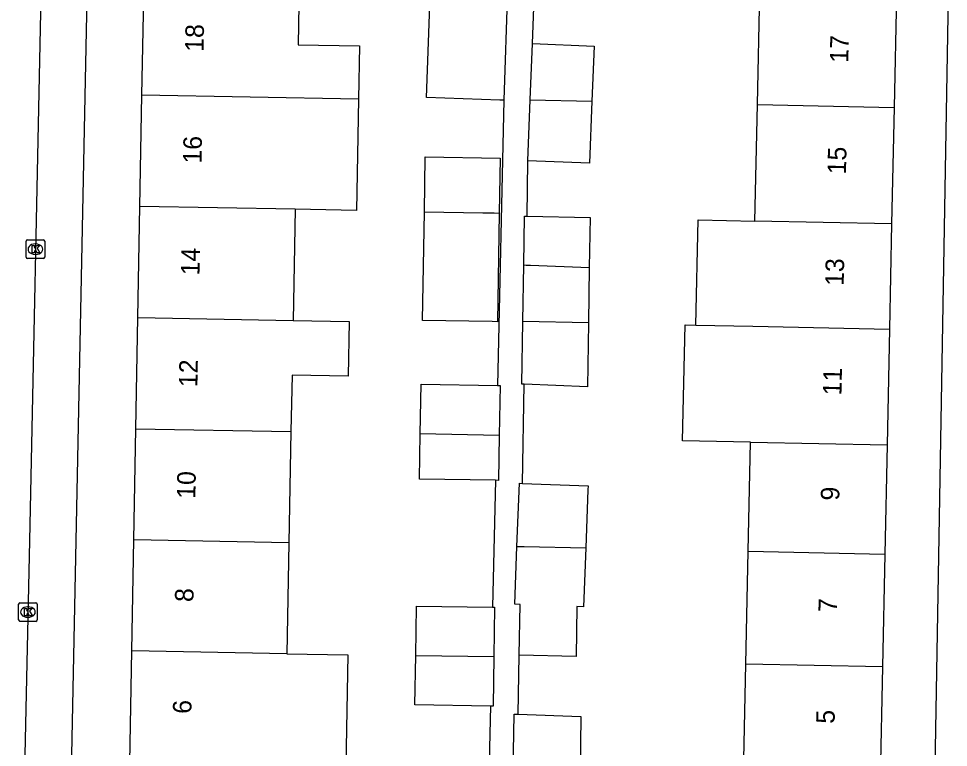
# Model space of a CAD drawing. Extents: x 160026 to 161302, y 384757 to 385701.
# Drawn here: x 160621.7 to 160671.9, y 385059.5 to 385098.8 of the extents above; entities that cross this region are included whole.
import ezdxf

# ---------------------------------------------------------------- set-up
doc = ezdxf.new("R2010")
doc.units = 0
for name, color, linetype in [('IMGEO_Kolk', 7, 'Continuous'), ('IMGEO_Pand', 7, 'Continuous'), ('IMGEO_Pand_nummerreeks', 7, 'Continuous'), ('IMGEO_Rijbaan_lokaal_open', 7, 'Continuous'), ('IMGEO_Voetpad_open', 7, 'Continuous')]:
    doc.layers.add(name, color=color, linetype=linetype)

msp = doc.modelspace()

# ---------------------------------------------------------------- linework, layer by layer
at = {"layer": 'IMGEO_Kolk'}
for p, q in [((160622.226, 385086.887), (160623.078, 385086.887)), ((160622.151, 385085.961), (160622.151, 385086.813)), ((160622.639, 385086.667), (160622.664, 385086.667)), ((160623.152, 385086.813), (160623.152, 385085.961)), ((160623.078, 385085.887), (160622.226, 385085.887)), ((160622.662, 385086.107), (160622.637, 385086.107)), ((160621.816, 385067.302), (160622.668, 385067.302)), ((160621.741, 385066.376), (160621.741, 385067.228)), ((160622.229, 385067.082), (160622.254, 385067.082)), ((160622.742, 385067.228), (160622.742, 385066.376)), ((160622.668, 385066.302), (160621.816, 385066.302)), ((160622.252, 385066.522), (160622.227, 385066.522))]:
    msp.add_line(p, q, dxfattribs=at)
for points in [[(160622.226, 385086.887), (160623.078, 385086.887)], [(160622.151, 385085.961), (160622.151, 385086.813)], [(160622.472, 385086.587), (160622.595, 385086.587), (160622.595, 385086.436), (160622.725, 385086.587), (160622.889, 385086.587), (160622.743, 385086.436), (160622.896, 385086.187), (160622.744, 385086.187), (160622.659, 385086.351), (160622.595, 385086.284), (160622.595, 385086.187), (160622.472, 385086.187), (160622.472, 385086.587)], [(160623.152, 385086.813), (160623.152, 385085.961)], [(160623.078, 385085.887), (160622.226, 385085.887)], [(160621.816, 385067.302), (160622.668, 385067.302)], [(160621.741, 385066.376), (160621.741, 385067.228)], [(160622.062, 385067.002), (160622.185, 385067.002), (160622.185, 385066.851), (160622.315, 385067.002), (160622.479, 385067.002), (160622.333, 385066.851), (160622.486, 385066.602), (160622.334, 385066.602), (160622.249, 385066.766), (160622.185, 385066.699), (160622.185, 385066.602), (160622.062, 385066.602), (160622.062, 385067.002)], [(160622.742, 385067.228), (160622.742, 385066.376)], [(160622.668, 385066.302), (160621.816, 385066.302)]]:
    msp.add_lwpolyline(points, dxfattribs=at)
for centre, start, end in [((160622.228, 385086.811), 91.552, 178.448), ((160622.228, 385086.811), 91.552, 178.448), ((160623.076, 385086.811), 1.552, 88.448), ((160623.076, 385086.811), 1.552, 88.448), ((160622.228, 385085.963), 181.552, 268.448), ((160622.228, 385085.963), 181.552, 268.448), ((160623.076, 385085.963), 271.552, 358.448), ((160623.076, 385085.963), 271.552, 358.448), ((160621.818, 385067.226), 91.552, 178.448), ((160621.818, 385067.226), 91.552, 178.448), ((160622.666, 385067.226), 1.552, 88.448), ((160622.666, 385067.226), 1.552, 88.448), ((160621.818, 385066.378), 181.552, 268.448), ((160621.818, 385066.378), 181.552, 268.448), ((160622.666, 385066.378), 271.552, 358.448), ((160622.666, 385066.378), 271.552, 358.448)]:
    msp.add_arc(centre, 0.0765, start, end, dxfattribs=at)
for centre, major_axis, ratio, start_param, end_param in [((160622.638, 385086.387), (-0.387, 0.002), 0.722429, 4.712389, 7.853982), ((160622.663, 385086.387), (-0.39, 0.002), 0.717154, 1.570796, 4.712389), ((160622.228, 385066.802), (-0.387, 0.002), 0.722429, 4.712389, 7.853982), ((160622.253, 385066.802), (-0.39, 0.002), 0.717154, 1.570796, 4.712389)]:
    msp.add_ellipse(centre, major_axis=major_axis, ratio=ratio, start_param=start_param, end_param=end_param, dxfattribs=at)
at = {"layer": 'IMGEO_Pand'}
for points in [[(160628.402, 385094.689), (160628.515, 385100.842)], [(160636.89, 385100.688), (160636.83, 385097.419), (160640.14, 385097.359), (160640.087, 385094.474)], [(160647.939, 385094.427), (160647.714, 385094.434), (160643.768, 385094.566), (160643.969, 385100.561)], [(160648.14, 385100.422), (160647.939, 385094.427)], [(160661.62, 385094.186), (160661.746, 385100.285)], [(160669.124, 385100.133), (160668.998, 385094.034)], [(160649.365, 385094.438), (160649.482, 385097.477)], [(160649.482, 385097.477), (160652.806, 385097.349), (160652.691, 385094.37)], [(160628.291, 385088.692), (160628.402, 385094.689)], [(160640.087, 385094.474), (160628.402, 385094.689)], [(160640.087, 385094.474), (160639.976, 385088.477), (160636.666, 385088.538)], [(160649.238, 385091.16), (160649.365, 385094.438)], [(160652.691, 385094.37), (160652.562, 385091.032), (160649.238, 385091.16)], [(160649.365, 385094.438), (160652.691, 385094.37)], [(160661.491, 385087.906), (160661.62, 385094.186)], [(160661.62, 385094.186), (160668.998, 385094.034)], [(160668.998, 385094.034), (160668.869, 385087.754)], [(160643.644, 385088.409), (160643.693, 385091.369), (160647.732, 385091.302), (160647.682, 385088.335)], [(160628.181, 385082.695), (160628.291, 385088.692)], [(160636.666, 385088.538), (160628.291, 385088.692)], [(160636.666, 385088.538), (160636.556, 385082.541)], [(160647.682, 385088.335), (160647.584, 385082.473), (160647.314, 385082.478), (160643.546, 385082.541), (160643.644, 385088.409)], [(160643.644, 385088.409), (160646.806, 385088.351), (160647.412, 385088.34), (160647.682, 385088.335)], [(160649.009, 385085.536), (160649.049, 385088.162), (160649.186, 385088.159)], [(160649.186, 385088.159), (160652.588, 385088.089), (160652.547, 385085.4)], [(160658.307, 385082.294), (160658.424, 385087.969), (160661.491, 385087.906)], [(160668.869, 385087.754), (160661.491, 385087.906)], [(160668.869, 385087.754), (160668.752, 385082.079)], [(160648.963, 385082.487), (160649.009, 385085.536)], [(160649.009, 385085.536), (160649.14, 385085.531), (160649.372, 385085.522), (160652.547, 385085.4)], [(160652.547, 385085.4), (160652.502, 385082.414)], [(160628.07, 385076.698), (160628.181, 385082.695)], [(160628.181, 385082.695), (160636.556, 385082.541)], [(160636.556, 385082.541), (160639.583, 385082.486), (160639.528, 385079.537), (160636.501, 385079.593), (160636.445, 385076.544)], [(160649.028, 385079.094), (160648.912, 385079.098), (160648.963, 385082.487)], [(160652.502, 385082.414), (160648.963, 385082.487)], [(160652.502, 385082.414), (160652.448, 385078.961), (160649.028, 385079.094)], [(160661.244, 385075.974), (160657.588, 385076.049), (160657.717, 385082.306), (160658.307, 385082.294)], [(160658.307, 385082.294), (160661.374, 385082.231), (160668.752, 385082.079)], [(160668.752, 385082.079), (160668.622, 385075.822)], [(160643.422, 385076.416), (160643.468, 385079.1), (160647.595, 385079.031)], [(160647.595, 385079.031), (160647.728, 385079.029), (160647.683, 385076.337)], [(160627.96, 385070.701), (160628.07, 385076.698)], [(160628.07, 385076.698), (160636.445, 385076.544)], [(160636.445, 385076.544), (160636.335, 385070.547)], [(160647.48, 385073.914), (160643.382, 385073.983), (160643.422, 385076.416)], [(160647.683, 385076.337), (160643.422, 385076.416)], [(160647.683, 385076.337), (160647.642, 385073.911), (160647.48, 385073.914)], [(160661.123, 385070.087), (160661.244, 385075.974)], [(160661.244, 385075.974), (160668.622, 385075.822)], [(160668.622, 385075.822), (160668.501, 385069.935)], [(160648.64, 385070.344), (160648.772, 385073.752), (160648.934, 385073.746)], [(160648.934, 385073.746), (160652.483, 385073.609), (160652.475, 385073.405), (160652.354, 385070.268)], [(160627.849, 385064.704), (160627.96, 385070.701)], [(160636.335, 385070.547), (160627.96, 385070.701)], [(160636.335, 385070.547), (160636.224, 385064.55)], [(160648.767, 385064.484), (160648.82, 385067.219), (160648.52, 385067.231), (160648.64, 385070.344)], [(160648.64, 385070.344), (160649.027, 385070.336), (160652.354, 385070.268)], [(160652.354, 385070.268), (160652.231, 385067.088), (160651.872, 385067.102), (160651.836, 385064.401), (160648.767, 385064.484)], [(160660.997, 385063.998), (160661.123, 385070.087)], [(160661.123, 385070.087), (160668.501, 385069.935)], [(160668.501, 385069.935), (160668.375, 385063.846)], [(160643.179, 385064.461), (160643.219, 385067.129), (160647.327, 385067.068)], [(160647.327, 385067.068), (160647.434, 385067.066), (160647.394, 385064.398)], [(160627.739, 385058.707), (160627.849, 385064.704)], [(160636.224, 385064.55), (160627.849, 385064.704)], [(160636.224, 385064.55), (160639.522, 385064.489), (160639.412, 385058.492), (160636.114, 385058.553)], [(160647.208, 385061.732), (160643.139, 385061.793), (160643.179, 385064.461)], [(160643.179, 385064.461), (160647.394, 385064.398)], [(160647.394, 385064.398), (160647.354, 385061.73), (160647.208, 385061.732)], [(160660.874, 385057.996), (160660.997, 385063.998)], [(160668.375, 385063.846), (160660.997, 385063.998)], [(160668.375, 385063.846), (160668.252, 385057.844)], [(160648.447, 385058.252), (160648.491, 385061.303), (160648.717, 385061.294)], [(160648.717, 385061.294), (160652.091, 385061.165), (160652.048, 385058.178)]]:
    msp.add_lwpolyline(points, dxfattribs=at)
at = {"layer": 'IMGEO_Rijbaan_lokaal_open'}
msp.add_lwpolyline([(160622.965, 385101.188), (160622.916, 385099.184), (160622.325, 385070.649), (160621.803, 385046.719)], dxfattribs=at)
at = {"layer": 'IMGEO_Voetpad_open'}
for points in [[(160625.445, 385100.857), (160624.337, 385046.664)], [(160649.482, 385097.477), (160649.595, 385100.412)], [(160670.994, 385045.891), (160671.933, 385100.035)], [(160647.939, 385094.427), (160647.595, 385079.031)], [(160649.186, 385088.159), (160649.238, 385091.16)], [(160648.934, 385073.746), (160649.028, 385079.094)], [(160647.48, 385073.914), (160647.327, 385067.068)], [(160648.717, 385061.294), (160648.767, 385064.484)], [(160647.208, 385061.732), (160647.056, 385054.955)]]:
    msp.add_lwpolyline(points, dxfattribs=at)

# ---------------------------------------------------------------- texts
at = {"layer": 'IMGEO_Pand_nummerreeks'}
for s, rotation, p in [('18', 88.9445, (160631.725, 385097.034)), ('17', 88.8181, (160666.528, 385096.439)), ('16', 88.9445, (160631.614, 385091.001)), ('15', 88.8181, (160666.403, 385090.418)), ('14', 88.9445, (160631.503, 385084.97)), ('13', 88.8199, (160666.279, 385084.397)), ('12', 88.9445, (160631.392, 385078.936)), ('11', 88.8199, (160666.158, 385078.49)), ('10', 88.9445, (160631.281, 385072.912)), ('9', 88.8181, (160666.04, 385072.814)), ('8', 88.9445, (160631.178, 385067.342)), ('7', 88.8181, (160665.915, 385066.792)), ('6', 88.9445, (160631.067, 385061.307)), ('5', 88.8181, (160665.791, 385060.771))]:
    msp.add_text(s, height=1, rotation=rotation, dxfattribs=at).set_placement(p)

doc.saveas('drawing.dxf')
